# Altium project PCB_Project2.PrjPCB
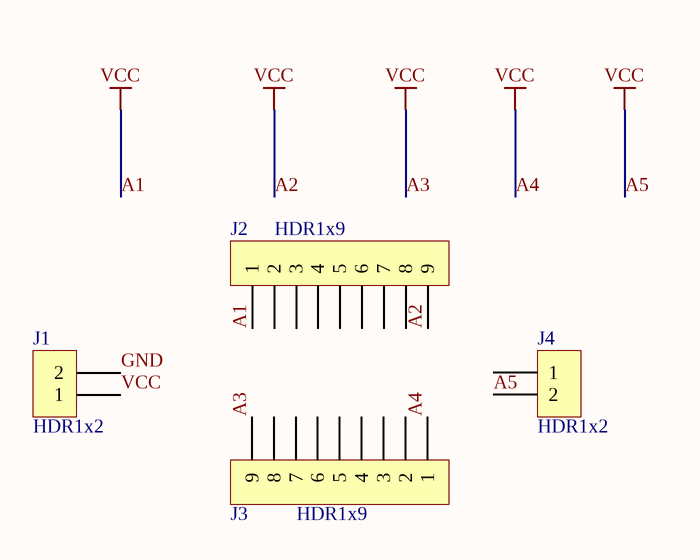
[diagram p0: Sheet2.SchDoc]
1 sheet, 4 parts. Net scope: global (net labels, ports and power ports of the same name join across sheets).
Board files: PCB2.PcbDoc, PCB2-1.PcbDoc

## Sheet Sheet2.SchDoc
size A4

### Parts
J1  HDR1x2  [PIN-2-2.54-1.0]
J2  HDR1x9  [PIN-9-2.54-1.0]
J3  HDR1x9  [PIN-9-2.54-1.0]
J4  HDR1x2  [PIN-2-2.54-1.0]

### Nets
A1: J1.1 J2.1 J2.9 J3.1 J3.9 J4.2  [also labelled A2, A3, A4, A5, VCC]
GND: J1.2

Not connected (* = marked no-connect by the designer): J2 2 3 4 5 6 7 8; J3 2 3 4 5 6 7 8; J4 1

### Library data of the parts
J1 J4 = HDR1x2: Connector
J2 J3 = HDR1x9: Connector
